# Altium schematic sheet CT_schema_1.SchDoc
size 430 x 400 mm
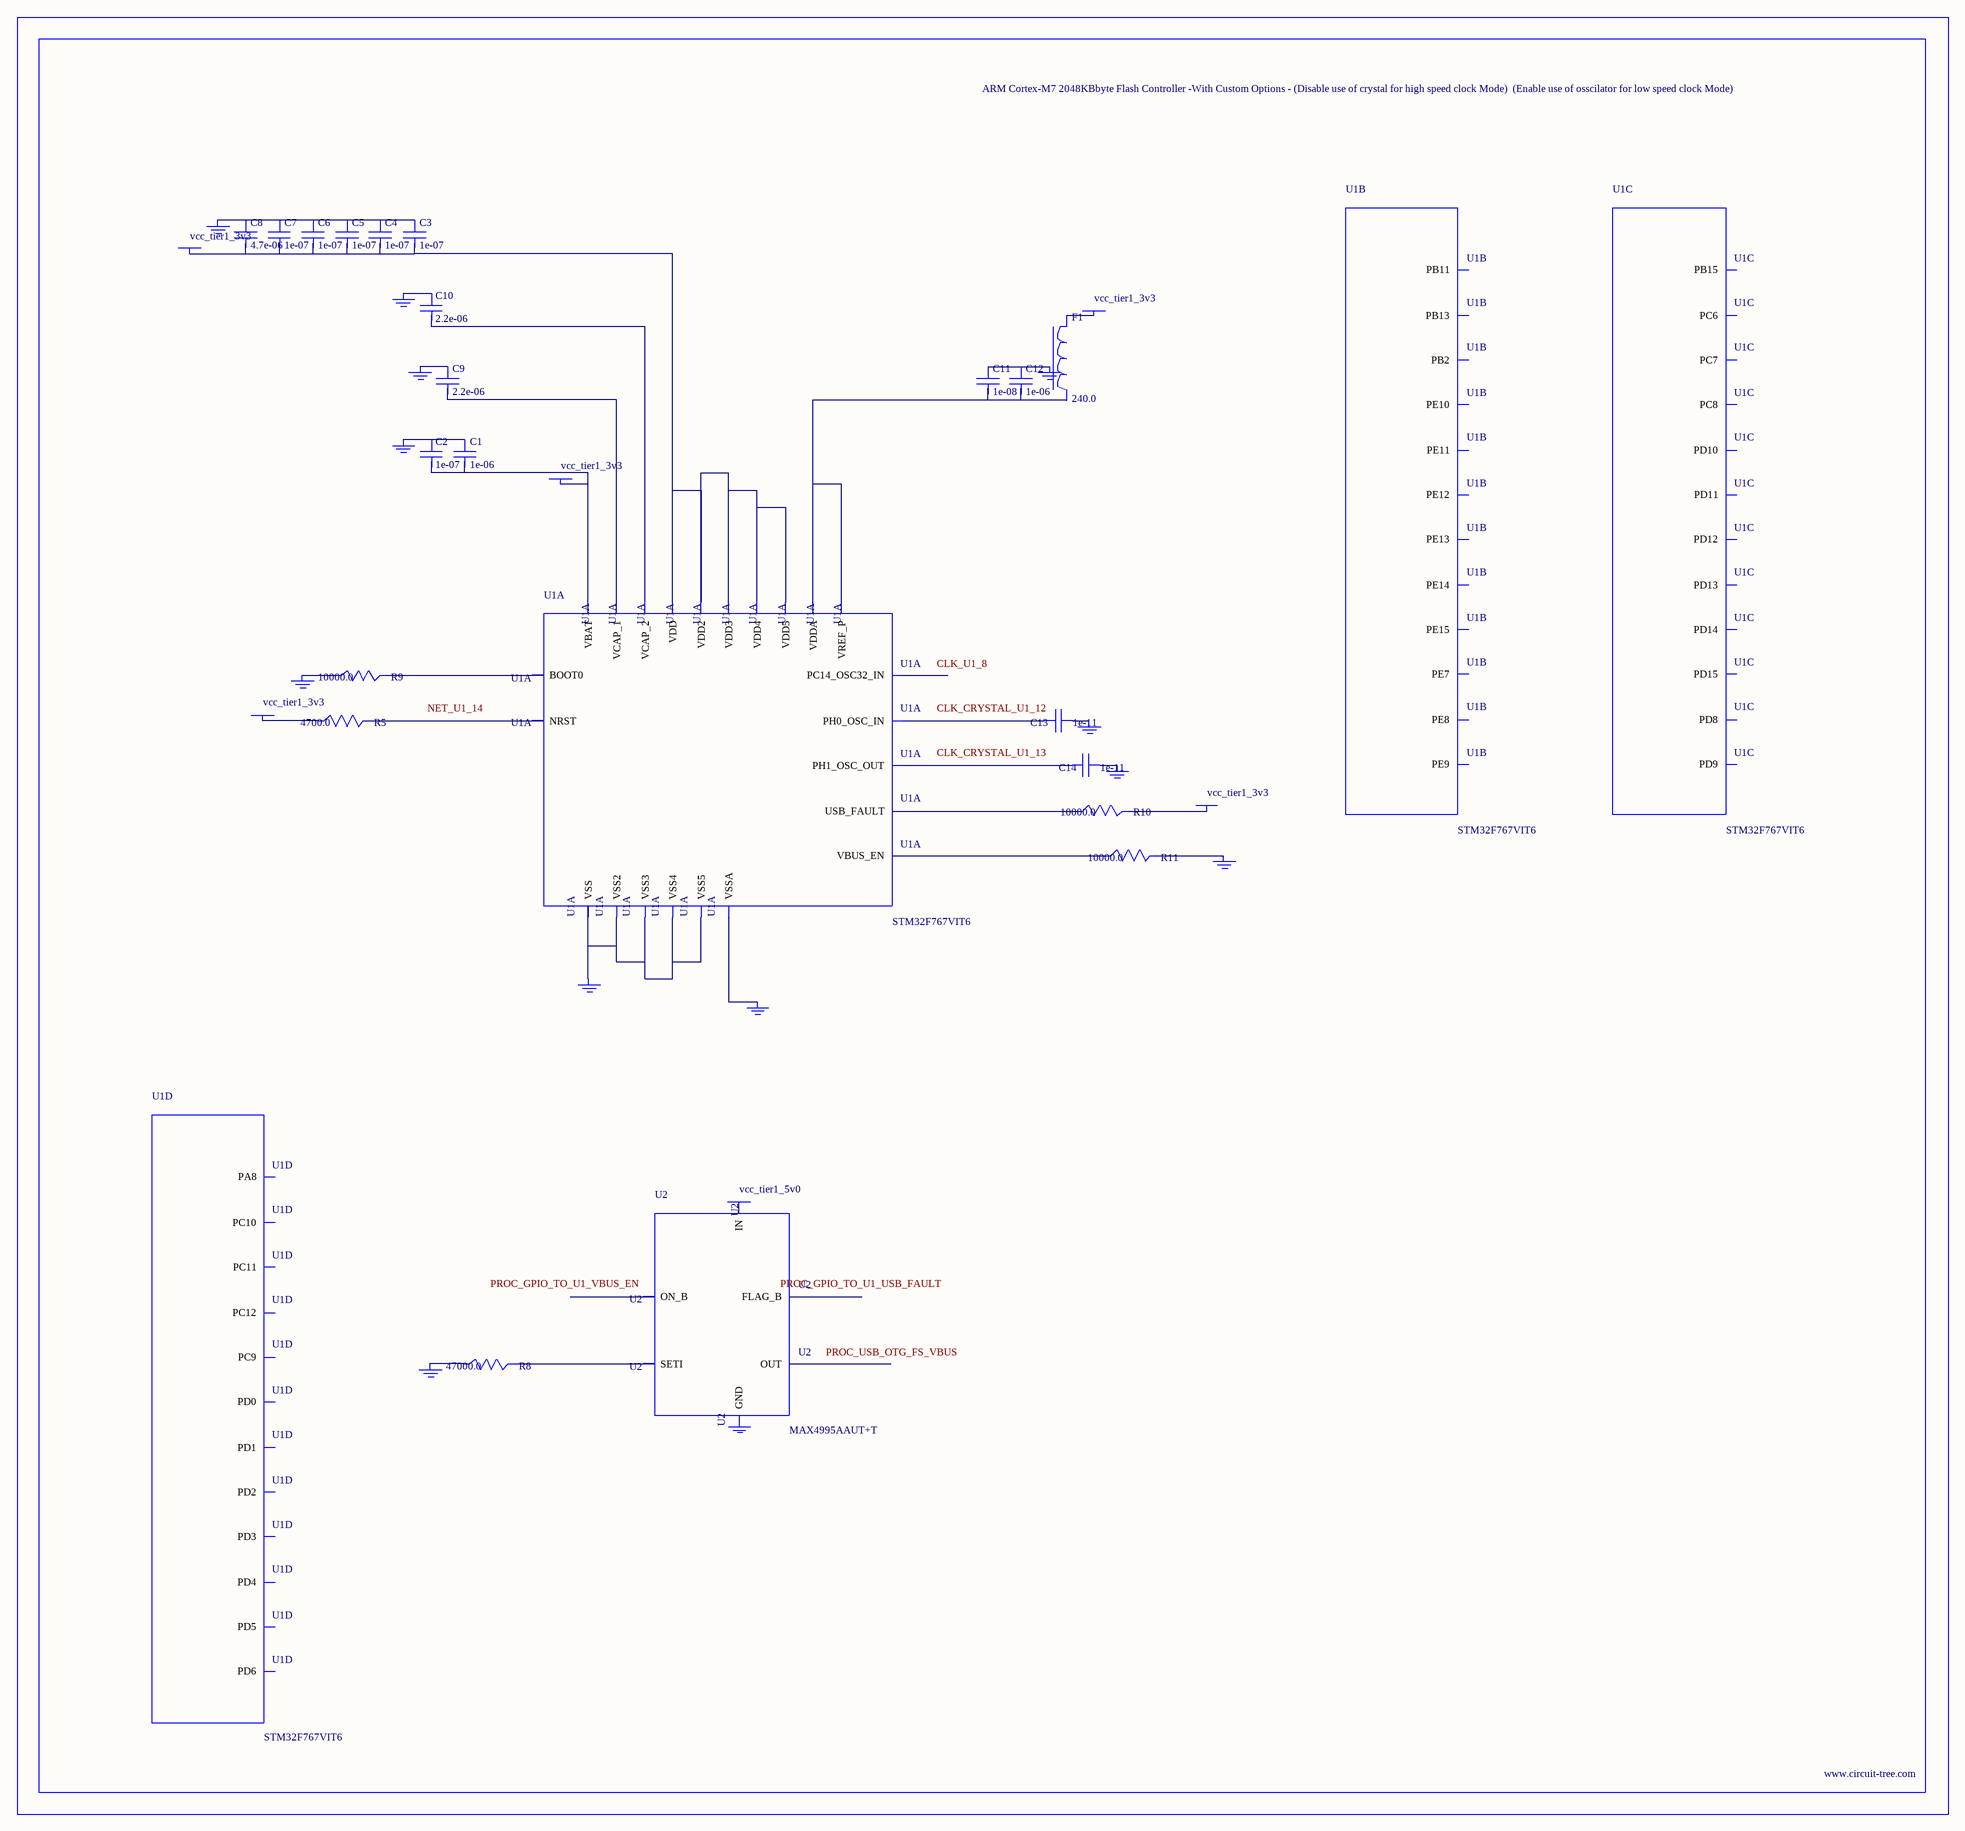
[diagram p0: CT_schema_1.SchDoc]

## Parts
BORDER0  (no value)
C1  1e-06  [C0603]
C2  1e-07  [C0603]
C3  1e-07  [C0603]
C4  1e-07  [C0603]
C5  1e-07  [C0603]
C6  1e-07  [C0603]
C7  1e-07  [C0603]
C8  4.7e-06  [C0603]
C9  2.2e-06  [C0603]
C10  2.2e-06  [C0603]
C11  1e-08  [C0603]
C12  1e-06  [C0603]
C13  1e-11  [C0402]
C14  1e-11  [C0402]
F1  240.0  [L0603]
GND_INSTANCE_0_0  (no value)
GND_INSTANCE_0_1  (no value)
GND_INSTANCE_0_2  (no value)
GND_INSTANCE_0_3  (no value)
GND_INSTANCE_0_4  (no value)
GND_INSTANCE_0_5  (no value)
GND_INSTANCE_0_6  (no value)
GND_INSTANCE_0_7  (no value)
GND_INSTANCE_0_8  (no value)
GND_INSTANCE_0_9  (no value)
GND_INSTANCE_0_10  (no value)
GND_INSTANCE_0_11  (no value)
GND_INSTANCE_0_12  (no value)
POWER_INSTANCE_0_0  vcc_tier1_3v3
POWER_INSTANCE_0_1  vcc_tier1_3v3
POWER_INSTANCE_0_2  vcc_tier1_3v3
POWER_INSTANCE_0_3  vcc_tier1_3v3
POWER_INSTANCE_0_4  vcc_tier1_3v3
POWER_INSTANCE_0_5  vcc_tier1_5v0
R5  4700.0  [R0603]
R8  47000.0  [R0603]
R9  10000.0  [R0603]
R10  10000.0  [R0603]
R11  10000.0  [R0603]
U1  STM32F767VIT6  [LQFP100]  (parts A,B,C,D of 11)
U2  MAX4995AAUT+T  [SOT-23-6]

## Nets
NetC1_1: C1.1 C2.1 GND_INSTANCE_0_1.0(GND)
NetC1_2: C1.2 C2.2 POWER_INSTANCE_0_1.0(PWR) U1.6(VBAT)
NetC3_1: C3.1 C4.1 C5.1 C6.1 C7.1 C8.1 GND_INSTANCE_0_2.0(GND)
NetC3_2: C3.2 C4.2 C5.2 C6.2 C7.2 C8.2 POWER_INSTANCE_0_2.0(PWR) U1.11(VDD) U1.27(VDD2) U1.50(VDD3) U1.75(VDD4) U1.100(VDD5)
NetC9_1: C9.1 GND_INSTANCE_0_7.0(GND)
NetC9_2: C9.2 U1.48(VCAP_1)
NetC10_1: C10.1 GND_INSTANCE_0_8.0(GND)
NetC10_2: C10.2 U1.73(VCAP_2)
NetC11_1: C11.1 C12.1 GND_INSTANCE_0_6.0(GND)
NetC11_2: C11.2 C12.2 U1.20(VREF_P) U1.21(VDDA)
NetC13_1: C13.1 GND_INSTANCE_0_3.0(GND)
NetC13_2: C13.2 U1.12(PH0_OSC_IN)
NetC14_1: C14.1 GND_INSTANCE_0_4.0(GND)
NetC14_2: C14.2 U1.13(PH1_OSC_OUT)
NetF1_1: F1.1 POWER_INSTANCE_0_3.0(PWR)
NetGND_INSTANCE_0_0_0: GND_INSTANCE_0_0.0(GND) R11.2
NetGND_INSTANCE_0_5_0: GND_INSTANCE_0_5.0(GND) U1.19(VSSA)
NetGND_INSTANCE_0_9_0: GND_INSTANCE_0_9.0(GND) R9.1
NetGND_INSTANCE_0_10_0: GND_INSTANCE_0_10.0(GND) U1.10(VSS) U1.26(VSS2) U1.49(VSS3) U1.74(VSS4) U1.99(VSS5)
NetGND_INSTANCE_0_11_0: GND_INSTANCE_0_11.0(GND) R8.1
NetPOWER_INSTANCE_0_0_0: POWER_INSTANCE_0_0.0(PWR) R10.2
NetPOWER_INSTANCE_0_4_0: POWER_INSTANCE_0_4.0(PWR) R5.1
NetR5_2: R5.2 U1.14(NRST)
NetR8_2: R8.2 U2.3(SETI)
NetR9_2: R9.2 U1.94(BOOT0)
NetR10_1: R10.1 U1.2(USB_FAULT)
NetR11_1: R11.1 U1.1(VBUS_EN)

Not connected (* = marked no-connect by the designer): F1 2; GND_INSTANCE_0_12 0(GND); POWER_INSTANCE_0_5 0(PWR); U1 8(PC14_OSC32_IN) 36(PB2) 37(PE7) 38(PE8) 39(PE9) 40(PE10) 41(PE11) 42(PE12) 43(PE13) 44(PE14) 45(PE15) 47(PB11) 52(PB13) 54(PB15) 55(PD8) 56(PD9) 57(PD10) 58(PD11) 59(PD12) 60(PD13) 61(PD14) 62(PD15) 63(PC6) 64(PC7) 65(PC8) 66(PC9) 67(PA8) 78(PC10) 79(PC11) 80(PC12) 81(PD0) 82(PD1) 83(PD2) 84(PD3) 85(PD4) 86(PD5) 87(PD6); U2 1(OUT) 2(GND) 4(ON_B) 5(IN) 6(FLAG_B)

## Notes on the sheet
- Labels drawn without touching a wire or pin: CLK_CRYSTAL_U1_12, CLK_CRYSTAL_U1_13, CLK_U1_8, NET_U1_14, PROC_GPIO_TO_U1_USB_FAULT, PROC_GPIO_TO_U1_VBUS_EN, PROC_USB_OTG_FS_VBUS

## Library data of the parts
BORDER0 = BORDER_PAGE0
C1 C12 = C0603C105K3RACTU
C2-C7 = 06035C104K4Z2A
C8 = GRM188R6YA475KE15D
C9 C10 = C0603C225K8RACTU
C11 = 06035C103K4Z2A
C13 C14 = C0402C100K3GACTU
F1 = Z0603C241ASMST
GND_INSTANCE_0_0-GND_INSTANCE_0_12 = GND
POWER_INSTANCE_0_0-POWER_INSTANCE_0_5 = PWR
R5 = RC0603JR-074K7L
R8 = RC0603JR-0747KL
R9-R11 = RC0603JR-0710KL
